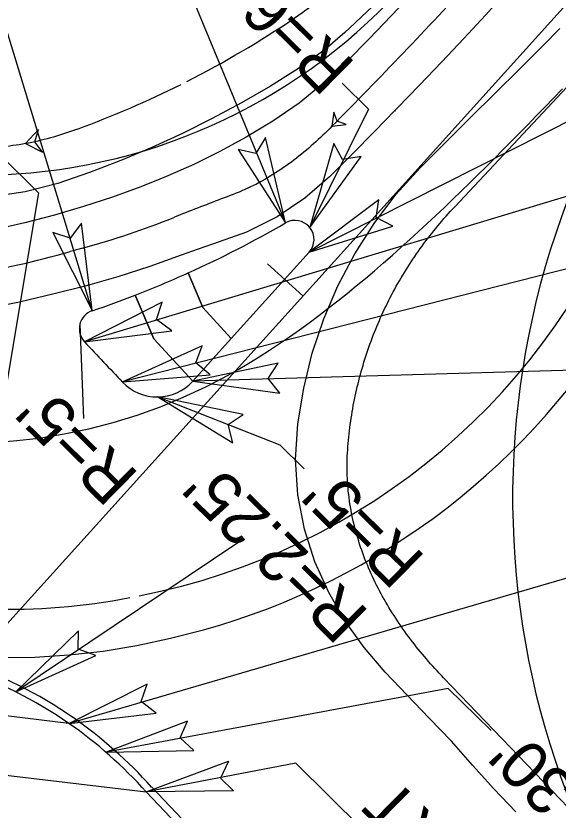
# Model space of a CAD drawing. Extents: x 1262642 to 1268358, y 767825 to 773481.
# Drawn here: x 1266795.4 to 1266852.1, y 772160.2 to 772243.3 of the extents above; entities that cross this region are included whole.
import ezdxf

# ---------------------------------------------------------------- set-up
doc = ezdxf.new("R2010")
doc.units = 0
for name, color, linetype in [('Prop Conc 1ft 6in Curb and Gutter', 7, 'Continuous'), ('Prop Conc 2ft 6in Curb and Gutter', 7, 'Continuous'), ('Prop Conc 5in Monolithic Keyed In Island', 7, 'Continuous'), ('Prop Dimension', 7, 'Continuous'), ('Prop Dimension Text', 7, 'Continuous'), ('Prop EOT', 7, 'Continuous'), ('Prop Horizontal Alignment', 7, 'Continuous'), ('Prop Horizontal Alignment Tick Small', 7, 'Continuous'), ('Prop Lane Lines', 7, 'Continuous'), ('Prop Shade Medium', 7, 'Continuous'), ('Prop Terminator CELL', 7, 'Continuous'), ('Scratch_Level_3', 7, 'Continuous')]:
    doc.layers.add(name, color=color, linetype=linetype)

msp = doc.modelspace()

# ---------------------------------------------------------------- linework, layer by layer
at = {"layer": 'Prop Conc 1ft 6in Curb and Gutter'}
for p, q in [((1266817.902, 772209.552), (1266826.047, 772218.568)), ((1266814.923, 772212.809), (1266813.379, 772216.41)), ((1266809.809, 772209.51), (1266807.846, 772214.09)), ((1266817.902, 772209.552), (1266814.923, 772212.809)), ((1266813.861, 772205.08), (1266809.809, 772209.51)), ((1266813.861, 772205.08), (1266817.902, 772209.552))]:
    msp.add_line(p, q, dxfattribs=at)
for centre, radius, start, end in [((1266767.027, 772319.192), 112.75, 294.27409, 300.09264), ((1266824.563, 772219.908), 2, 317.90382, 120.09264), ((1266767.027, 772319.192), 112.75, 291.22464, 294.27409), ((1266767.027, 772319.192), 112.75, 288.79513, 291.22464), ((1266803.998, 772210.561), 2, 108.79513, 223.46272), ((1275046.434, 780022.154), 11358, 223.4627212, 223.4918815), ((1266810.151, 772208.431), 5, 223.49188, 317.90382)]:
    msp.add_arc(centre, radius, start, end, dxfattribs=at)
at = {"layer": 'Prop Conc 2ft 6in Curb and Gutter'}
for p, q in [((1266800.905, 772169.279), (1266758.086, 772174.32)), ((1266766.008, 772167.185), (1266808.991, 772162.125))]:
    msp.add_line(p, q, dxfattribs=at)
msp.add_arc((1266773.813, 772130.513), 47.295, 41.9434, 55.05159, dxfattribs=at)
at = {"layer": 'Prop Conc 5in Monolithic Keyed In Island'}
for p, q in [((1266800.905, 772169.279), (1266758.086, 772174.32)), ((1266766.008, 772167.185), (1266808.991, 772162.125))]:
    msp.add_line(p, q, dxfattribs=at)
for centre, radius, start, end in [((1266775.238, 772132.318), 45, 55.22254, 71.69984), ((1266773.813, 772130.513), 47.295, 41.9434, 55.05159), ((1275047.307, 780021.225), 11385.75, 223.6505027, 224.2564693)]:
    msp.add_arc(centre, radius, start, end, dxfattribs=at)
at = {"layer": 'Prop Dimension'}
msp.add_line((1266803.354, 772212.453), (1266784.103, 772275.524), dxfattribs=at)
at = {"layer": 'Prop Dimension Text'}
for p, q in [((1266769.21, 772252.901), (1266797.725, 772224.805)), ((1266829.504, 772236.274), (1266832.261, 772233.557)), ((1266802.056, 772211.04), (1266802.431, 772201.172)), ((1266810.212, 772203.432), (1266822.996, 772198.415)), ((1266822.996, 772198.415), (1266825.524, 772195.924)), ((1266840.617, 772172.936), (1266845.093, 772168.526)), ((1266851.227, 772138.936), (1266824.646, 772165.127))]:
    msp.add_line(p, q, dxfattribs=at)
for points in [[(1266796.901, 772286.072), (1266823.56, 772221.639)], [(1266927.819, 772269.993), (1266826.047, 772218.568)], [(1266915.078, 772243.134), (1266802.546, 772209.185)], [(1266832.261, 772233.557), (1266826.113, 772221.162)], [(1266899.269, 772228.602), (1266806.543, 772204.999)], [(1266797.725, 772224.805), (1266789.373, 772175.059)], [(1266893.769, 772207.388), (1266813.883, 772205.081)], [(1266883.239, 772193.314), (1266800.924, 772169.283)], [(1266818.571, 772188.167), (1266795.356, 772172.588)], [(1266840.617, 772172.936), (1266804.789, 772166.273)], [(1266824.646, 772165.127), (1266808.991, 772162.125)]]:
    msp.add_lwpolyline(points, dxfattribs=at)
at = {"layer": 'Prop EOT'}
for centre, radius, start, end in [((1266775.238, 772132.318), 45.75, 55.22254, 71.69984), ((1266773.813, 772130.513), 48.045, 41.9434, 55.05159), ((1275047.307, 780021.225), 11385, 223.6505027, 224.2564693)]:
    msp.add_arc(centre, radius, start, end, dxfattribs=at)
at = {"layer": 'Prop Horizontal Alignment'}
msp.add_line((1266770.936, 772153.71), (1267443.049, 772897.651), dxfattribs=at)
msp.add_arc((1275047.307, 780021.225), 11400, 222.9935866, 225.4043192, dxfattribs=at)
at = {"layer": 'Prop Horizontal Alignment Tick Small'}
msp.add_line((1266825.405, 772214), (1266821.695, 772217.352), dxfattribs=at)
at = {"layer": 'Prop Lane Lines'}
for centre, radius, start, end in [((1266791.4, 772286.629), 60, 223.13275, 315.73419), ((1266934.351, 772192.878), 87, 146.70968, 223.92648), ((1275047.307, 780021.225), 11427, 222.9935866, 225.3637298)]:
    msp.add_arc(centre, radius, start, end, dxfattribs=at)
at = {"layer": 'Prop Shade Medium'}
for p, q in [((1266817.902, 772209.552), (1266826.047, 772218.568)), ((1266813.379, 772216.41), (1266814.923, 772212.809)), ((1266807.846, 772214.09), (1266809.809, 772209.51)), ((1266814.923, 772212.809), (1266817.902, 772209.552)), ((1266809.809, 772209.51), (1266813.861, 772205.08)), ((1266800.905, 772169.279), (1266758.086, 772174.32)), ((1266766.008, 772167.185), (1266808.991, 772162.125))]:
    msp.add_line(p, q, dxfattribs=at)
for centre, radius, start, end in [((1266767.027, 772319.192), 112.75, 294.27409, 300.09264), ((1266824.563, 772219.908), 2, 317.90382, 120.09264), ((1266767.027, 772319.192), 112.75, 288.79513, 291.22464), ((1266803.998, 772210.561), 2, 108.79513, 223.46272), ((1275046.434, 780022.154), 11358, 223.4627212, 223.4918815), ((1266810.151, 772208.431), 5, 223.49188, 317.90382), ((1266775.238, 772132.318), 45, 55.22254, 71.69984), ((1275047.307, 780021.225), 11385.75, 223.6505027, 224.2564693)]:
    msp.add_arc(centre, radius, start, end, dxfattribs=at)
at = {"layer": 'Prop Terminator CELL'}
for points in [[(1266818.616, 772229.317), (1266823.56, 772221.639), (1266821.496, 772230.594), (1266820.473, 772228.91)], [(1266828.643, 772229.937), (1266826.113, 772221.162), (1266831.499, 772228.608), (1266829.558, 772228.271)], [(1266833.333, 772224.074), (1266826.047, 772218.568), (1266834.822, 772221.298), (1266833.066, 772222.192)], [(1266799.235, 772220.644), (1266803.336, 772212.484), (1266802.234, 772221.608), (1266801.038, 772220.042)], [(1266810.677, 772213.343), (1266802.546, 772209.185), (1266811.663, 772210.351), (1266810.088, 772211.536)], [(1266814.848, 772208.798), (1266806.543, 772204.999), (1266815.701, 772205.765), (1266814.181, 772207.018)], [(1266822.817, 772206.972), (1266813.883, 772205.081), (1266822.987, 772203.827), (1266821.777, 772205.382)], [(1266819.156, 772201.587), (1266810.212, 772203.432), (1266818.052, 772198.636), (1266817.566, 772200.546)], [(1266801.907, 772178.951), (1266795.356, 772172.588), (1266803.728, 772176.38), (1266801.875, 772177.05)], [(1266809.092, 772173.368), (1266800.924, 772169.283), (1266810.05, 772170.367), (1266808.487, 772171.567)], [(1266813.324, 772169.521), (1266804.789, 772166.273), (1266813.977, 772166.439), (1266812.542, 772167.788)], [(1266818.123, 772162.214), (1266808.991, 772162.125), (1266817.608, 772165.321), (1266816.763, 772163.541)]]:
    msp.add_lwpolyline(points, close=True, dxfattribs=at)
at = {"layer": 'Scratch_Level_3'}
for p, q in [((1266841.285, 772223.318), (1266947.116, 772336.274)), ((1266869.722, 772143.248), (1266840.121, 772174.045))]:
    msp.add_line(p, q, dxfattribs=at)
for points in [[(1266851.927, 772262.23), (1266849.399, 772259.392), (1266846.869, 772256.557), (1266844.324, 772253.736), (1266841.761, 772250.93), (1266839.181, 772248.14), (1266839.181, 772248.14), (1266839.181, 772248.14), (1266836.91, 772245.712), (1266834.627, 772243.297), (1266832.329, 772240.896), (1266829.992, 772238.533), (1266829.754, 772238.301)], [(1266857.154, 772257.575), (1266854.638, 772254.726), (1266852.109, 772251.89), (1266849.572, 772249.061), (1266847.045, 772246.223), (1266844.518, 772243.386), (1266844.518, 772243.386), (1266842.236, 772240.925), (1266839.928, 772238.482), (1266837.606, 772236.051), (1266835.271, 772233.632), (1266835.036, 772233.391)], [(1266830.211, 772247.671), (1266829.97, 772247.442), (1266829.727, 772247.213), (1266829.482, 772246.987), (1266829.236, 772246.762), (1266828.988, 772246.539), (1266828.739, 772246.318), (1266828.488, 772246.099), (1266828.235, 772245.882), (1266827.98, 772245.666), (1266827.724, 772245.453), (1266827.467, 772245.242), (1266827.207, 772245.032), (1266826.946, 772244.825), (1266826.683, 772244.62), (1266826.419, 772244.417), (1266826.152, 772244.217), (1266825.885, 772244.018), (1266825.615, 772243.822), (1266825.344, 772243.629), (1266825.071, 772243.437), (1266824.796, 772243.249), (1266824.52, 772243.062)], [(1266832.706, 772244.314), (1266830.272, 772242.015), (1266829.781, 772241.557)], [(1266847.698, 772160.029), (1266845.4, 772162.449), (1266843.143, 772164.908), (1266840.94, 772167.42), (1266838.628, 772169.826), (1266836.315, 772172.232), (1266834.008, 772174.644), (1266831.824, 772177.205), (1266829.839, 772179.984), (1266828.1, 772182.984), (1266826.655, 772186.198), (1266825.558, 772189.609), (1266824.863, 772193.185), (1266824.623, 772196.879), (1266824.875, 772200.63), (1266825.479, 772204.355), (1266826.383, 772208.019), (1266827.582, 772211.598), (1266829.068, 772215.068), (1266830.831, 772218.406), (1266832.859, 772221.59), (1266835.139, 772224.599), (1266837.656, 772227.412), (1266840.316, 772230.063), (1266842.939, 772232.657), (1266845.519, 772235.21), (1266848.06, 772237.731), (1266850.565, 772240.23), (1266852.298, 772241.968)], [(1266829.781, 772241.557), (1266827.725, 772239.796), (1266824.951, 772237.782), (1266821.992, 772235.95), (1266818.974, 772234.206), (1266815.907, 772232.551), (1266812.794, 772230.985), (1266809.603, 772229.527), (1266806.353, 772228.171), (1266803.061, 772226.916), (1266799.74, 772225.768), (1266796.344, 772224.878), (1266792.813, 772224.356)], [(1266829.754, 772238.301), (1266827.563, 772236.265), (1266824.994, 772234.16), (1266822.264, 772232.279), (1266819.477, 772230.61), (1266816.704, 772229.11), (1266813.974, 772227.77), (1266811.273, 772226.57), (1266810.439, 772226.223)], [(1266815.459, 772204.613), (1266816.377, 772205.083), (1266817.51, 772205.691), (1266818.628, 772206.319), (1266819.731, 772206.967), (1266820.818, 772207.633), (1266821.892, 772208.316), (1266822.951, 772209.015), (1266823.997, 772209.729), (1266825.03, 772210.455), (1266826.051, 772211.195), (1266827.06, 772211.945), (1266828.057, 772212.706), (1266829.044, 772213.477), (1266830.021, 772214.257), (1266830.987, 772215.045), (1266831.944, 772215.841), (1266832.892, 772216.644), (1266833.832, 772217.453), (1266834.764, 772218.269), (1266835.687, 772219.089), (1266836.604, 772219.916), (1266837.513, 772220.746), (1266838.416, 772221.582), (1266839.313, 772222.421), (1266840.203, 772223.263), (1266841.088, 772224.11), (1266841.968, 772224.959), (1266842.843, 772225.811), (1266843.713, 772226.665), (1266844.579, 772227.522), (1266845.44, 772228.38), (1266846.302, 772229.245), (1266847.17, 772230.12), (1266848.044, 772231.008), (1266848.927, 772231.908), (1266849.826, 772232.83), (1266850.727, 772233.757), (1266851.639, 772234.7), (1266852.566, 772235.66)], [(1266835.036, 772233.391), (1266832.923, 772231.226), (1266830.561, 772228.833), (1266828.182, 772226.459), (1266825.597, 772224.235), (1266822.705, 772222.273), (1266819.501, 772220.664), (1266816.057, 772219.442), (1266815.03, 772219.095)], [(1266801.816, 772231.463), (1266801.503, 772231.348), (1266801.189, 772231.236), (1266800.874, 772231.127), (1266800.558, 772231.021), (1266800.241, 772230.919), (1266799.923, 772230.819), (1266799.604, 772230.723), (1266799.284, 772230.629), (1266798.963, 772230.539), (1266798.641, 772230.453), (1266798.318, 772230.369), (1266797.994, 772230.289), (1266797.67, 772230.212), (1266797.345, 772230.139), (1266797.019, 772230.069), (1266796.692, 772230.003), (1266796.365, 772229.941)], [(1266828.442, 772231.752), (1266828.208, 772231.515), (1266827.971, 772231.28), (1266827.733, 772231.047), (1266827.493, 772230.816), (1266827.251, 772230.587), (1266827.007, 772230.359), (1266826.762, 772230.134), (1266826.514, 772229.911), (1266826.264, 772229.691), (1266826.012, 772229.472), (1266825.758, 772229.256), (1266825.502, 772229.043), (1266825.244, 772228.832), (1266824.984, 772228.623), (1266824.722, 772228.418), (1266824.457, 772228.215), (1266824.19, 772228.015), (1266823.921, 772227.818), (1266823.65, 772227.624), (1266823.377, 772227.433), (1266823.102, 772227.245), (1266822.824, 772227.061), (1266822.544, 772226.88), (1266822.262, 772226.702), (1266821.978, 772226.528), (1266821.692, 772226.357), (1266821.403, 772226.19), (1266821.112, 772226.027), (1266820.819, 772225.868), (1266820.525, 772225.713), (1266820.227, 772225.562), (1266819.928, 772225.415), (1266819.627, 772225.272), (1266819.324, 772225.133), (1266819.019, 772224.999), (1266818.712, 772224.869), (1266818.403, 772224.744)], [(1266796.365, 772229.941), (1266796.037, 772229.882), (1266795.708, 772229.826), (1266795.379, 772229.775), (1266795.049, 772229.727), (1266794.718, 772229.683), (1266794.388, 772229.642), (1266794.056, 772229.606), (1266793.724, 772229.573), (1266793.392, 772229.545), (1266793.06, 772229.52), (1266792.727, 772229.5), (1266792.394, 772229.483), (1266792.061, 772229.47), (1266791.728, 772229.462), (1266791.395, 772229.458), (1266791.061, 772229.458), (1266790.728, 772229.462), (1266790.395, 772229.47), (1266790.062, 772229.483), (1266789.729, 772229.5)], [(1266810.439, 772226.223), (1266808.442, 772225.431), (1266805.472, 772224.344), (1266802.442, 772223.344), (1266799.381, 772222.442), (1266796.299, 772221.64), (1266793.197, 772220.939), (1266792.886, 772220.875)], [(1266818.403, 772224.744), (1266818.092, 772224.624), (1266817.781, 772224.504), (1266817.47, 772224.384), (1266817.159, 772224.265), (1266816.847, 772224.146), (1266816.536, 772224.027), (1266816.225, 772223.908), (1266815.913, 772223.789), (1266815.602, 772223.67), (1266815.291, 772223.55), (1266814.979, 772223.431), (1266814.668, 772223.311), (1266814.357, 772223.191), (1266814.046, 772223.071), (1266813.736, 772222.95), (1266813.425, 772222.829), (1266813.115, 772222.707), (1266812.805, 772222.584), (1266812.495, 772222.461), (1266812.186, 772222.337), (1266811.877, 772222.212)], [(1266840.121, 772174.045), (1266839.892, 772174.286), (1266839.664, 772174.53), (1266839.437, 772174.774), (1266839.213, 772175.021), (1266838.99, 772175.268), (1266838.768, 772175.518), (1266838.549, 772175.768), (1266838.331, 772176.021), (1266838.115, 772176.275), (1266837.901, 772176.53), (1266837.689, 772176.787), (1266837.478, 772177.046), (1266837.27, 772177.306), (1266837.064, 772177.568), (1266836.859, 772177.831), (1266836.657, 772178.096), (1266836.457, 772178.363), (1266836.259, 772178.631), (1266836.063, 772178.901), (1266835.87, 772179.172), (1266835.679, 772179.445), (1266835.49, 772179.72), (1266835.304, 772179.996), (1266835.12, 772180.274), (1266834.938, 772180.554), (1266834.759, 772180.835), (1266834.583, 772181.118), (1266834.409, 772181.402), (1266834.238, 772181.689), (1266834.069, 772181.976), (1266833.904, 772182.265), (1266833.741, 772182.556), (1266833.581, 772182.849), (1266833.423, 772183.142), (1266833.269, 772183.438), (1266833.118, 772183.735), (1266832.969, 772184.033), (1266832.824, 772184.333), (1266832.682, 772184.635), (1266832.543, 772184.938), (1266832.407, 772185.242), (1266832.275, 772185.548), (1266832.145, 772185.855), (1266832.02, 772186.164), (1266831.897, 772186.474), (1266831.778, 772186.785), (1266831.662, 772187.098), (1266831.55, 772187.412), (1266831.442, 772187.727), (1266831.337, 772188.044), (1266831.236, 772188.361), (1266831.138, 772188.68), (1266831.045, 772189), (1266830.955, 772189.321), (1266830.869, 772189.643), (1266830.786, 772189.966), (1266830.708, 772190.29), (1266830.634, 772190.615), (1266830.564, 772190.941), (1266830.498, 772191.267), (1266830.436, 772191.595), (1266830.378, 772191.923), (1266830.324, 772192.252), (1266830.275, 772192.582), (1266830.229, 772192.912), (1266830.189, 772193.243), (1266830.152, 772193.574), (1266830.12, 772193.906), (1266830.092, 772194.238), (1266830.069, 772194.571), (1266830.05, 772194.904), (1266830.036, 772195.237), (1266830.027, 772195.57), (1266830.022, 772195.903), (1266830.022, 772196.236), (1266830.026, 772196.57), (1266830.035, 772196.903), (1266830.049, 772197.236), (1266830.068, 772197.569), (1266830.09, 772197.901), (1266830.114, 772198.234), (1266830.141, 772198.566), (1266830.171, 772198.898), (1266830.204, 772199.23), (1266830.239, 772199.561), (1266830.277, 772199.892), (1266830.318, 772200.223), (1266830.361, 772200.554), (1266830.407, 772200.884), (1266830.456, 772201.214), (1266830.507, 772201.543), (1266830.561, 772201.872), (1266830.618, 772202.2), (1266830.677, 772202.528), (1266830.739, 772202.856), (1266830.804, 772203.183), (1266830.871, 772203.509), (1266830.942, 772203.835), (1266831.014, 772204.161), (1266831.089, 772204.485), (1266831.167, 772204.809), (1266831.248, 772205.133), (1266831.331, 772205.456), (1266831.417, 772205.778), (1266831.506, 772206.099), (1266831.597, 772206.42), (1266831.69, 772206.74), (1266831.787, 772207.059), (1266831.885, 772207.377), (1266831.987, 772207.695), (1266832.091, 772208.011), (1266832.197, 772208.327), (1266832.307, 772208.642), (1266832.418, 772208.956), (1266832.533, 772209.269), (1266832.649, 772209.581), (1266832.769, 772209.893), (1266832.891, 772210.203), (1266833.015, 772210.512), (1266833.142, 772210.82), (1266833.271, 772211.128), (1266833.403, 772211.434), (1266833.537, 772211.739), (1266833.674, 772212.043), (1266833.814, 772212.346), (1266833.955, 772212.647), (1266834.1, 772212.948), (1266834.246, 772213.247), (1266834.395, 772213.545), (1266834.547, 772213.842), (1266834.701, 772214.138), (1266834.857, 772214.432), (1266835.016, 772214.725), (1266835.177, 772215.017), (1266835.34, 772215.308), (1266835.506, 772215.597), (1266835.674, 772215.885), (1266835.845, 772216.171), (1266836.018, 772216.456), (1266836.193, 772216.74), (1266836.37, 772217.022), (1266836.55, 772217.303), (1266836.732, 772217.582), (1266836.916, 772217.86), (1266837.103, 772218.136), (1266837.291, 772218.411), (1266837.482, 772218.684), (1266837.675, 772218.956), (1266837.871, 772219.226), (1266838.068, 772219.494), (1266838.268, 772219.761), (1266838.47, 772220.026), (1266838.674, 772220.29), (1266838.88, 772220.552), (1266839.089, 772220.812), (1266839.299, 772221.071), (1266839.512, 772221.327), (1266839.726, 772221.582), (1266839.943, 772221.836), (1266840.162, 772222.087), (1266840.382, 772222.337), (1266840.605, 772222.585), (1266840.83, 772222.831), (1266841.057, 772223.075), (1266841.285, 772223.318)], [(1266815.03, 772219.095), (1266812.669, 772218.281), (1266809.361, 772217.085), (1266806.013, 772215.99), (1266802.623, 772215.032), (1266799.231, 772214.189), (1266795.89, 772213.396), (1266795.555, 772213.322)], [(1266802.318, 772218.996), (1266801.997, 772218.909), (1266801.675, 772218.822), (1266801.354, 772218.733), (1266801.033, 772218.643)], [(1266795.555, 772213.322), (1266792.526, 772212.711)], [(1266758.054, 772206.709), (1266759.789, 772205.836), (1266762.724, 772204.476), (1266765.71, 772203.241), (1266768.74, 772202.14), (1266771.799, 772201.18), (1266774.867, 772200.369), (1266777.932, 772199.711), (1266780.996, 772199.204), (1266783.988, 772198.853), (1266786.887, 772198.651), (1266789.688, 772198.586), (1266792.42, 772198.647), (1266795.121, 772198.831), (1266797.787, 772199.135), (1266800.414, 772199.559), (1266803.004, 772200.1), (1266805.549, 772200.756), (1266808.059, 772201.531), (1266810.499, 772202.411), (1266812.883, 772203.399), (1266815.228, 772204.498), (1266815.459, 772204.613)], [(1266815.341, 772179.168), (1266816.715, 772179.571), (1266818.42, 772180.113), (1266820.112, 772180.695), (1266821.79, 772181.318), (1266823.452, 772181.981), (1266825.098, 772182.684), (1266826.727, 772183.426), (1266828.337, 772184.208), (1266829.928, 772185.028), (1266831.499, 772185.886), (1266833.048, 772186.782), (1266834.576, 772187.714), (1266836.081, 772188.684), (1266837.562, 772189.689), (1266839.018, 772190.73), (1266840.449, 772191.806), (1266841.854, 772192.915), (1266843.231, 772194.058), (1266844.581, 772195.235), (1266845.902, 772196.443), (1266847.193, 772197.683), (1266848.454, 772198.953), (1266849.684, 772200.254), (1266850.883, 772201.583), (1266852.049, 772202.942), (1266853.182, 772204.328)], [(1266748.494, 772196.274), (1266750.108, 772195.021), (1266752.825, 772192.967), (1266755.573, 772190.956), (1266758.353, 772188.988), (1266761.164, 772187.064), (1266764.004, 772185.184), (1266766.874, 772183.349), (1266769.78, 772181.571), (1266772.846, 772180.001), (1266776.103, 772178.723), (1266779.535, 772177.787), (1266783.056, 772177.117), (1266786.607, 772176.625), (1266790.178, 772176.311), (1266793.761, 772176.178), (1266797.345, 772176.224), (1266800.923, 772176.45), (1266804.486, 772176.855), (1266808.023, 772177.439), (1266811.527, 772178.196), (1266814.996, 772179.071), (1266815.341, 772179.168)]]:
    msp.add_lwpolyline(points, dxfattribs=at)
for points in [[(1266828.442, 772231.752), (1266829.928, 772231.956), (1266828.97, 772232.285), (1266828.631, 772233.24)], [(1266796.365, 772229.941), (1266798.144, 772229.027), (1266797.349, 772230.12), (1266797.707, 772231.423)]]:
    msp.add_lwpolyline(points, close=True, dxfattribs=at)
for centre in [(1266835.036, 772233.391), (1266835.036, 772233.391), (1266828.442, 772231.752), (1266828.442, 772231.752)]:
    msp.add_circle(centre, 0.0417, dxfattribs=at)
for centre, radius, start, end in [((1266387.332, 772668.474), 620.729, 315.286422, 317.261141), ((1266760.381, 772339.12), 115.503, 297.24943, 303.73144), ((1266764.179, 772333.881), 109.115, 290.17755, 296.38587), ((1266795.073, 772250.677), 69.311, 280.97456, 339.76471), ((1266780.867, 772298.565), 82.41, 285.08776, 292.10379), ((1266773.012, 772317.337), 102.595, 273.27619, 285.84978), ((1266794.626, 772247.573), 66.349, 255.38768, 280.99965)]:
    msp.add_arc(centre, radius, start, end, dxfattribs=at)

# ---------------------------------------------------------------- texts
at = {"layer": 'Prop Dimension'}
for s, rotation, p in [("R=5'", 135.42387, (1266808.381, 772195.306)), ("R=2.25'", 135.42387, (1266832.46, 772180.881)), ("R=5'", 135.42387, (1266838.354, 772186.634)), ("R=47.30'", 134.2575, (1266866.855, 772149.774))]:
    msp.add_text(s, height=5, rotation=rotation, dxfattribs=at).set_placement(p)
at = {"layer": 'Prop Dimension Text'}
for s, p in [("R=60'", (1266831.041, 772238.278)), ("12.75' RT", (1266855.416, 772143.61))]:
    msp.add_text(s, height=5, rotation=135.42387, dxfattribs=at).set_placement(p)

doc.saveas('drawing.dxf')
